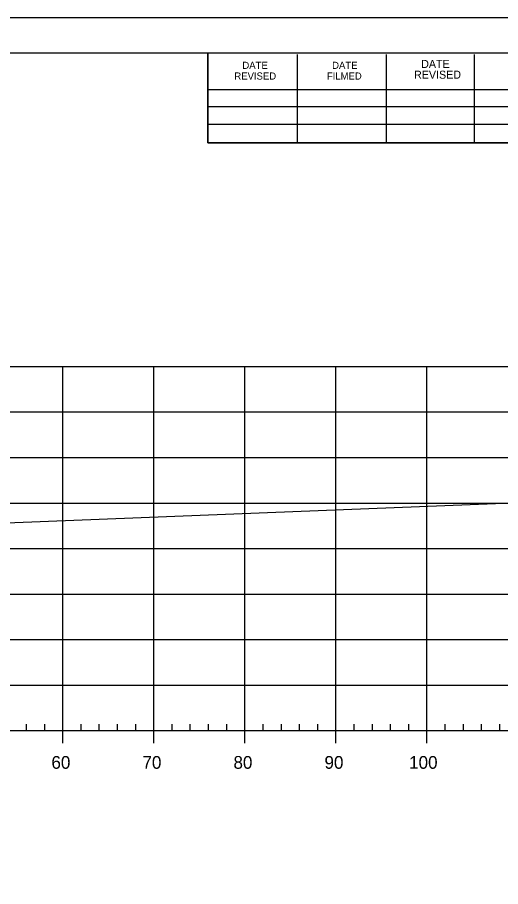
# Model space of a CAD drawing. Extents: x 1370843 to 1371177, y 380307 to 382654.
# Drawn here: x 1371068.7 to 1371121.8, y 382558.7 to 382654.2 of the extents above; entities that cross this region are included whole.
import ezdxf

# ---------------------------------------------------------------- set-up
doc = ezdxf.new("R2010")
doc.units = 0
for name, color, linetype in [('R_Axis', 7, 'Continuous'), ('R_Axis Annot', 7, 'Continuous'), ('R_Border', 7, 'Continuous'), ('R_Exist Surface', 7, 'Continuous'), ('R_Grid', 7, 'Continuous'), ('R_No Plot', 7, 'Continuous')]:
    doc.layers.add(name, color=color, linetype=linetype)

msp = doc.modelspace()

# ---------------------------------------------------------------- linework, layer by layer
at = {"layer": 'R_Axis'}
for p, q in [((1370868.709, 382575.828), (1371158.709, 382575.828)), ((1371069.709, 382575.828), (1371069.709, 382576.528)), ((1371071.709, 382575.828), (1371071.709, 382576.528)), ((1371073.709, 382574.428), (1371073.709, 382575.828)), ((1371075.709, 382575.828), (1371075.709, 382576.528)), ((1371077.709, 382575.828), (1371077.709, 382576.528)), ((1371079.709, 382575.828), (1371079.709, 382576.528)), ((1371081.709, 382575.828), (1371081.709, 382576.528)), ((1371083.709, 382574.428), (1371083.709, 382575.828)), ((1371085.709, 382575.828), (1371085.709, 382576.528)), ((1371087.709, 382575.828), (1371087.709, 382576.528)), ((1371089.709, 382575.828), (1371089.709, 382576.528)), ((1371091.709, 382575.828), (1371091.709, 382576.528)), ((1371093.709, 382574.428), (1371093.709, 382575.828)), ((1371095.709, 382575.828), (1371095.709, 382576.528)), ((1371097.709, 382575.828), (1371097.709, 382576.528)), ((1371099.709, 382575.828), (1371099.709, 382576.528)), ((1371101.709, 382575.828), (1371101.709, 382576.528)), ((1371103.709, 382574.428), (1371103.709, 382575.828)), ((1371105.709, 382575.828), (1371105.709, 382576.528)), ((1371107.709, 382575.828), (1371107.709, 382576.528)), ((1371109.709, 382575.828), (1371109.709, 382576.528)), ((1371111.709, 382575.828), (1371111.709, 382576.528)), ((1371113.709, 382574.428), (1371113.709, 382575.828)), ((1371115.709, 382575.828), (1371115.709, 382576.528)), ((1371117.709, 382575.828), (1371117.709, 382576.528)), ((1371119.709, 382575.828), (1371119.709, 382576.528)), ((1371121.709, 382575.828), (1371121.709, 382576.528))]:
    msp.add_line(p, q, dxfattribs=at)
at = {"layer": 'R_Border'}
for p, q in [((1370855.709, 382650.288), (1371171.889, 382650.288)), ((1371089.629, 382640.408), (1371089.629, 382650.288)), ((1371099.489, 382640.408), (1371099.489, 382650.088)), ((1371109.249, 382640.408), (1371109.249, 382650.088)), ((1371118.929, 382640.408), (1371118.929, 382650.088)), ((1371089.629, 382646.268), (1371128.789, 382646.268)), ((1371089.629, 382644.408), (1371128.789, 382644.408)), ((1371089.629, 382640.408), (1371089.629, 382642.468)), ((1371089.629, 382642.468), (1371128.789, 382642.468)), ((1371171.889, 382640.408), (1371089.629, 382640.408))]:
    msp.add_line(p, q, dxfattribs=at)
at = {"layer": 'R_Exist Surface'}
msp.add_line((1371098.98, 382599.884), (1371158.709, 382602.255), dxfattribs=at)
msp.add_lwpolyline([(1371064.7, 382598.523), (1371098.98, 382599.884)], dxfattribs=at)
at = {"layer": 'R_Grid'}
for p, q in [((1370868.709, 382615.828), (1371158.709, 382615.828)), ((1371073.709, 382575.828), (1371073.709, 382615.828)), ((1371083.709, 382575.828), (1371083.709, 382615.828)), ((1371093.709, 382575.828), (1371093.709, 382615.828)), ((1371103.709, 382575.828), (1371103.709, 382615.828)), ((1371113.709, 382575.828), (1371113.709, 382615.828)), ((1370868.709, 382610.828), (1371158.709, 382610.828)), ((1370868.709, 382605.828), (1371158.709, 382605.828)), ((1370868.709, 382600.828), (1371158.709, 382600.828)), ((1370868.709, 382595.828), (1371158.709, 382595.828)), ((1370868.709, 382590.828), (1371158.709, 382590.828)), ((1370868.709, 382585.828), (1371158.709, 382585.828)), ((1370868.709, 382580.828), (1371158.709, 382580.828)), ((1370868.709, 382575.828), (1371158.709, 382575.828))]:
    msp.add_line(p, q, dxfattribs=at)
at = {"layer": 'R_No Plot'}
msp.add_line((1370843.308, 382654.183), (1371176.642, 382654.183), dxfattribs=at)
for points in [[(1370843.302, 382654.183), (1371176.642, 382654.183), (1371176.642, 382440.845), (1370843.302, 382440.845)], [(1371089.629, 382650.288), (1371089.629, 382640.408), (1371125.361, 382640.408), (1371125.361, 382637.488), (1371148.561, 382637.488), (1371148.561, 382613.156), (1371171.889, 382613.156), (1371171.889, 382444.828), (1370855.709, 382444.828), (1370855.709, 382650.288)]]:
    msp.add_lwpolyline(points, close=True, dxfattribs=at)

# ---------------------------------------------------------------- texts
at = {"layer": 'R_Axis Annot'}
for s, p in [('60', (1371072.448, 382571.628)), ('70', (1371082.448, 382571.628)), ('80', (1371092.448, 382571.628)), ('90', (1371102.448, 382571.628)), ('100', (1371111.748, 382571.628))]:
    msp.add_text(s, height=1.4, dxfattribs=at).set_placement(p)
at = {"layer": 'R_Border'}
for s, height, p in [('DATE', 0.7819, (1371093.429, 382648.528)), ('DATE', 0.7819, (1371103.289, 382648.528)), ('DATE', 0.8792, (1371113.069, 382648.628)), ('REVISED', 0.8792, (1371112.289, 382647.448)), ('REVISED', 0.7819, (1371092.549, 382647.348)), ('FILMED', 0.7819, (1371102.709, 382647.348))]:
    msp.add_text(s, height=height, rotation=360, dxfattribs=at).set_placement(p)

doc.saveas('drawing.dxf')
